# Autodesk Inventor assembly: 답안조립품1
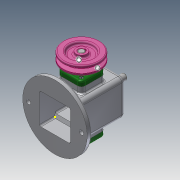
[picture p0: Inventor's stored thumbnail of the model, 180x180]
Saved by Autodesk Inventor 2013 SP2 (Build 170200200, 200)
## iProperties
Created: 2021-08
Part Number: 답안조립품1
Document SubType Name: Assembly
Designer: kumcom17
Author: kumcom17
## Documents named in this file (16)
- C:\Users\kumcom17\Desktop\710806V1005\답안조립품1.iam
- C:\Users\kumcom17\Desktop\710806V1005\본체.ipt
- C:\Users\kumcom17\Desktop\710806V1005\앞커버.ipt
- C:\Users\kumcom17\Desktop\710806V1005\뒤커버.ipt
- C:\Users\kumcom17\Desktop\710806V1005\베어링 12x32x10.ipt
- C:\Users\kumcom17\Desktop\710806V1005\편심축.ipt
- C:\Users\kumcom17\Desktop\710806V1005\키 4x4x10.ipt
- C:\Users\kumcom17\Desktop\710806V1005\V벨트풀리.ipt
- C:\Users\kumcom17\Desktop\710806V1005\오일 실 12 25 7.ipt
- C:\Users\kumcom17\Desktop\710806V1005\볼트 M4.ipt
- C:\Users\kumcom17\Desktop\710806V1005\링크.ipt
- C:\Users\kumcom17\Desktop\710806V1005\핀 5x18.ipt
- C:\Users\kumcom17\Desktop\710806V1005\고정핀 1.2x8.ipt
- C:\Users\kumcom17\Desktop\710806V1005\슬라이드.ipt
- C:\Users\kumcom17\Desktop\710806V1005\부시.ipt
- C:\Users\kumcom17\Desktop\710806V1005\멈춤나사 M3x8.ipt
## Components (3 placed, 3 different names)
1. V벨트풀리:1 — 각도:2
2. 핀 5x18:1
3. 고정핀 1.2x8:1
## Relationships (1: Angle 1)
- 각도:2 [Angle]: V벨트풀리:1
